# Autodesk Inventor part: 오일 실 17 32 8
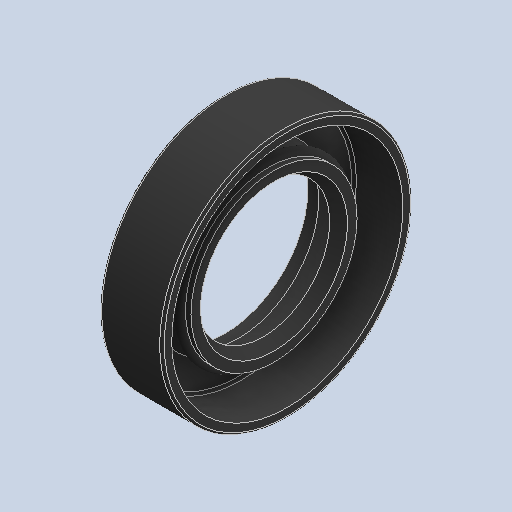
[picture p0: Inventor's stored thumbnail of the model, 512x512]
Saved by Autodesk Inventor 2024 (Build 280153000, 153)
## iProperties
Created: 2026-01
Part Number: 오일 실 17 32 8
Material: 고무
Description: 오일-실
Document SubType Name: Modeling
Designer: 2-10
Density: 0.93 g/cm^3
Appearance: 기본값
Author: jhkim
Sending System: Autodesk Inventor 2026
Preprocessor: ST-DEVELOPER v20.1
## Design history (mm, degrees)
node "오일 실 17 32 81"
node "솔리드1"
body "Solid1"
